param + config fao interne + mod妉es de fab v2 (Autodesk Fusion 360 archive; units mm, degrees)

design "param + config fao interne + modèles de fab"
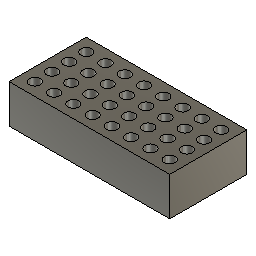
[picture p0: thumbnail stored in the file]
part number: Configuration 1
part number: Configuration 2
part number: Configuration 3
external_derived "Esquisse1" bodies "Corps1"
derived_instance "DerivedInstance1"
external_derived "Esquisse1" bodies "Corps1"
derived_instance "DerivedInstance2"
external_derived "Esquisse1" bodies "Corps1"
derived_instance "DerivedInstance3"
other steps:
derived_base_feature "Fonction de base dérivée1" bodies "Corps1"
derived_base_feature "Fonction de base dérivée1" bodies "Corps1"
derived_base_feature "Fonction de base dérivée1" bodies "Corps1"
create_component "CreateComponent1"
create_component "CreateComponent2"
create_component "CreateComponent3"
named bodies: "Corps1"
